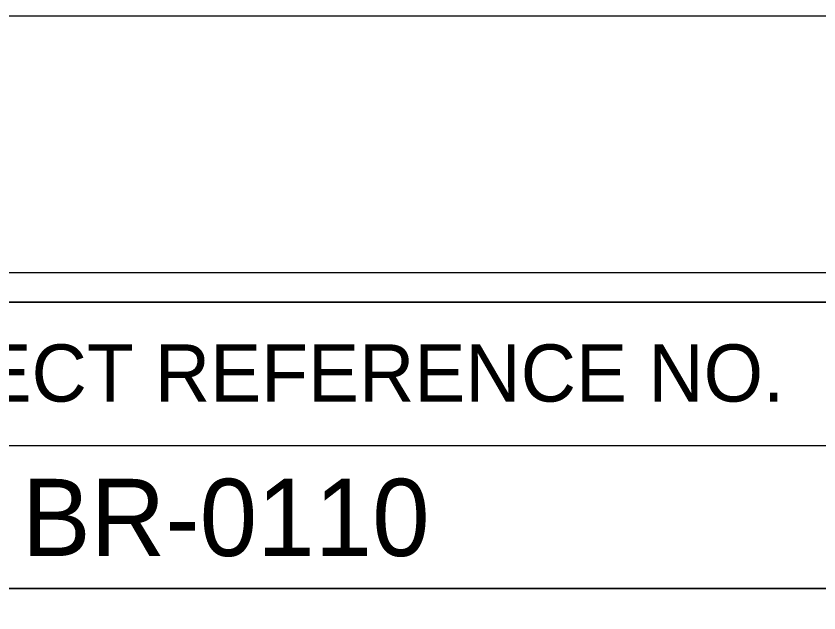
# Model space of a CAD drawing. Extents: x 1298931 to 1298964.7, y 1260142.8 to 1260164.8.
# Drawn here: x 1298961.193 to 1298962.595, y 1260163.721 to 1260164.764 of the extents above; entities that cross this region are included whole.
import ezdxf

# ---------------------------------------------------------------- set-up
doc = ezdxf.new("R2010")
doc.units = 0
for name, color, linetype in [('Sheet Cutting Line CELL', 7, 'Continuous'), ('Sheet Data Field CELL', 7, 'Continuous'), ('Sheet Plot Border Inside CELL', 7, 'Continuous'), ('Sheet Plot Border Outside CELL', 7, 'Continuous'), ('Sheet Summary Combination CELL', 7, 'Continuous'), ('Sheet Typical CELL', 7, 'Continuous')]:
    doc.layers.add(name, color=color, linetype=linetype)

msp = doc.modelspace()

# ---------------------------------------------------------------- linework, layer by layer
at = {"layer": 'Sheet Cutting Line CELL'}
msp.add_line((1298964.6711, 1260164.7641), (1298930.9911, 1260164.7641), dxfattribs=at)
at = {"layer": 'Sheet Plot Border Inside CELL'}
msp.add_lwpolyline([(1298964.5811, 1260164.3151), (1298931.2511, 1260164.3151), (1298931.2511, 1260143.2131), (1298964.5811, 1260143.2131)], close=True, dxfattribs=at)
at = {"layer": 'Sheet Plot Border Outside CELL'}
msp.add_lwpolyline([(1298964.6711, 1260164.7641), (1298930.9911, 1260164.7641), (1298930.9911, 1260142.7641), (1298964.6711, 1260142.7641)], close=True, dxfattribs=at)
at = {"layer": 'Sheet Summary Combination CELL'}
for p, q in [((1298960.3301, 1260164.0131), (1298964.3311, 1260164.0131)), ((1298960.3301, 1260163.7631), (1298964.3311, 1260163.7631))]:
    msp.add_line(p, q, dxfattribs=at)
for points in [[(1298964.3311, 1260164.2641), (1298934.3311, 1260164.2641), (1298934.3311, 1260143.2641), (1298964.3311, 1260143.2641)], [(1298960.3301, 1260164.2641), (1298964.3311, 1260164.2641), (1298964.3311, 1260163.7631), (1298960.3301, 1260163.7631)]]:
    msp.add_lwpolyline(points, close=True, dxfattribs=at)
at = {"layer": 'Sheet Typical CELL'}
msp.add_lwpolyline([(1298964.3308, 1260163.7631), (1298960.3301, 1260163.7631), (1298960.3301, 1260163.0596), (1298964.3308, 1260163.0596)], close=True, dxfattribs=at)

# ---------------------------------------------------------------- texts
at = {"layer": 'Sheet Data Field CELL'}
msp.add_text('BR-0110', height=0.135, dxfattribs=at).set_placement((1298961.2028, 1260163.8201))
at = {"layer": 'Sheet Summary Combination CELL'}
msp.add_text('PROJECT REFERENCE NO.', height=0.100002, dxfattribs=at).set_placement((1298960.7741, 1260164.0901))

doc.saveas('drawing.dxf')
